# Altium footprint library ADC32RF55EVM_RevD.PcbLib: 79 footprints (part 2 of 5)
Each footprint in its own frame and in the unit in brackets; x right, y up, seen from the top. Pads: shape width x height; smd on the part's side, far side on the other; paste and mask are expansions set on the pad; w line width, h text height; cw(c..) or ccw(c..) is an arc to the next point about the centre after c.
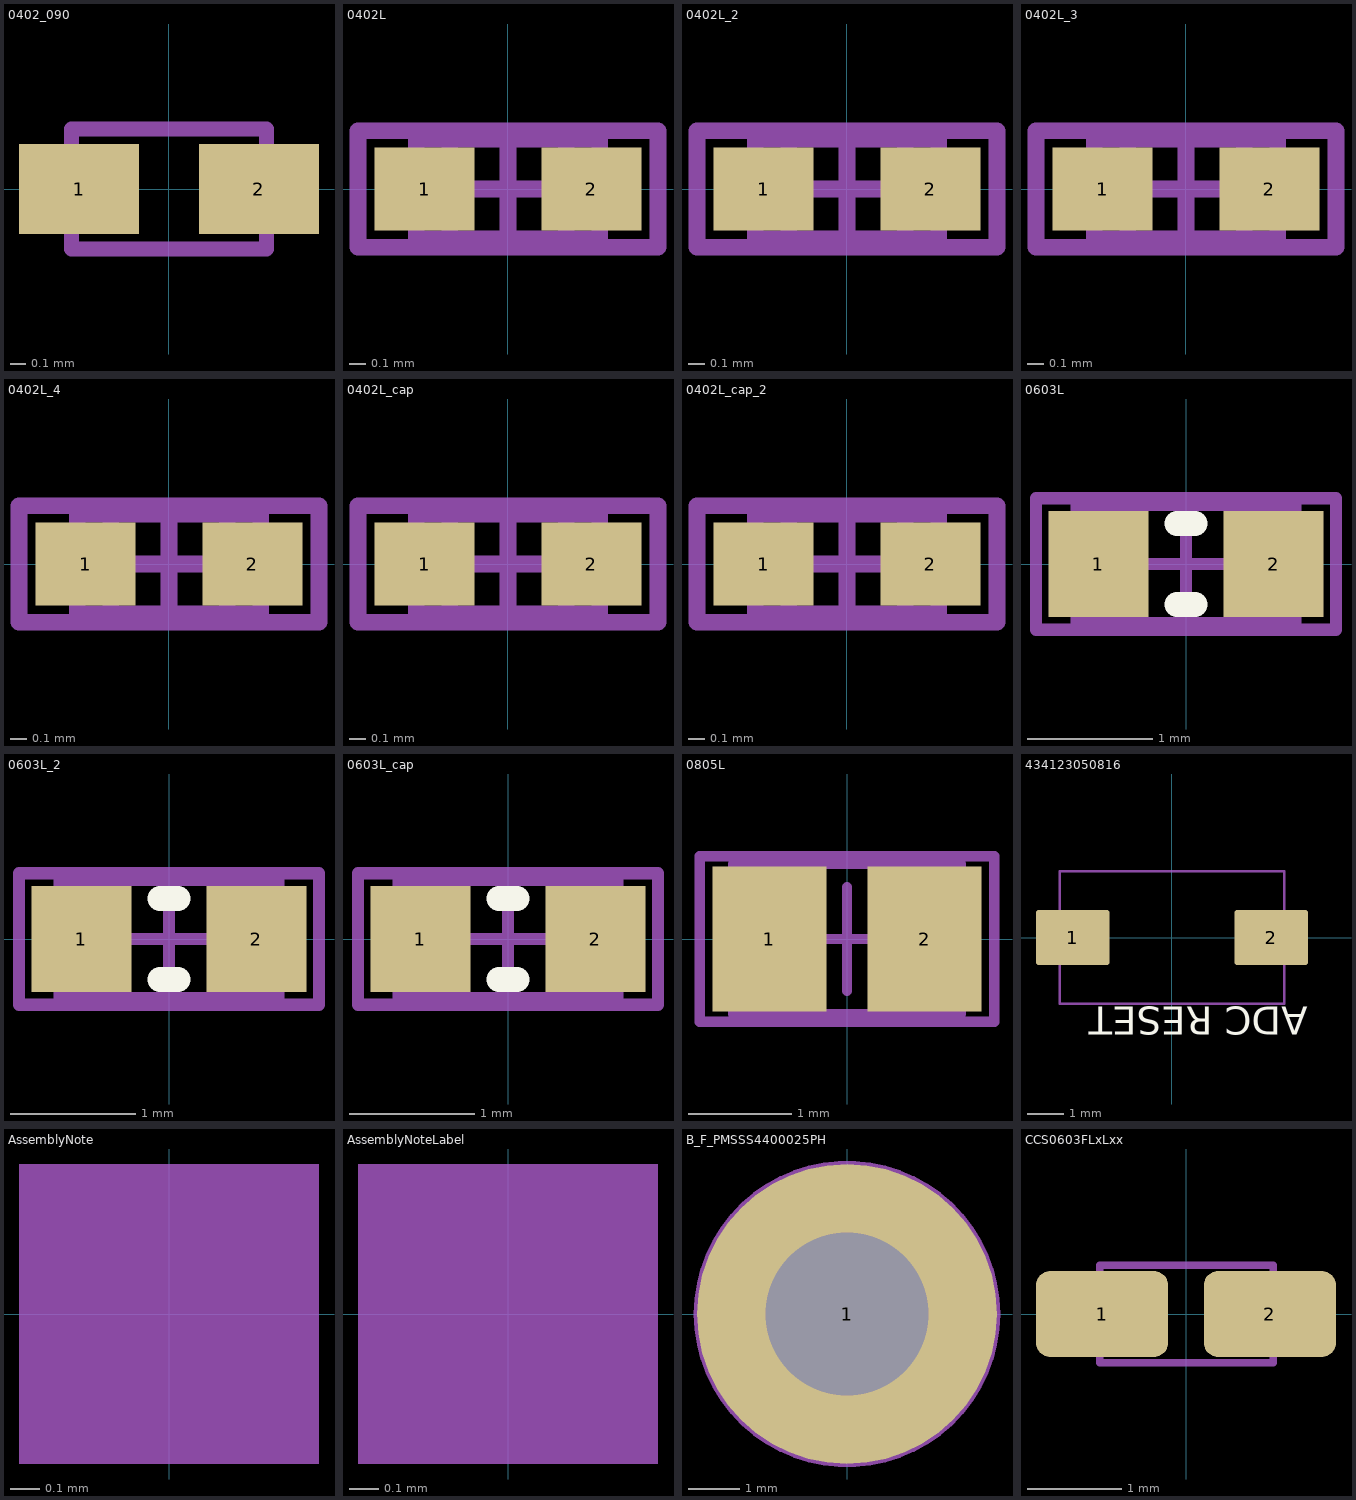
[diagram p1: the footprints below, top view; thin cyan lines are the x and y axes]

## 0402_090 [mm] "SMD, 2-Leads, Body 1x0.5mm"
height 0.9
pads (2):
  rect 0.8x0.6 smd: 1(-0.6,0) 2(0.6,0)
Mechanical 5:
  lines w0.1: -0.65,-0.4 -0.65,0.4 0.65,0.4 0.65,-0.4 -0.65,-0.4
  text ".Designator" at -0.55,-0.1 h0.3
3D body "CAPC1005X09N.step": height 0.9, standoff 0, extent -0.6,-0.35 0.6,0.35

## 0402L [mm] "0402 from SM-752 data"
height 0.6
pads (2):
  rect 0.6x0.5 smd: 1(-0.5,0) 2(0.5,0)
Mechanical 5:
  lines w0.1: -0.9,-0.35 -0.9,0.35 0.9,0.35 0.9,-0.35 -0.9,-0.35
  text ".Designator" at -0.254,0 h0.64
Mechanical 13:
  lines w0.1: -0.35,-0.3 -0.35,0.3 ; 0.35,-0.3 0.35,0.3 ; -0.55,-0.3 0.55,-0.3 0.55,0.3 -0.55,0.3 -0.55,-0.3
Mechanical 15:
  lines w0.1: -0.3,0 0.3,0 ; 0,-0.3 0,0.3 ; -0.9,-0.35 0.9,-0.35 0.9,0.35 -0.9,0.35 -0.9,-0.35
3D body: height 0.6, standoff 0, extent 0.351,-0.299 0.549,0.299
3D body: height 0.6, standoff 0, extent -0.349,-0.299 0.349,0.299
3D body: height 0.6, standoff 0, extent -0.549,-0.299 -0.351,0.299

## 0402L_2 [mm]
pads (2):
  rect 0.6x0.5 smd: 1(-0.5,0) 2(0.5,0)
Mechanical 5:
  lines w0.1: -0.9,-0.35 0.9,-0.35 0.9,0.35 -0.9,0.35 -0.9,-0.35
  text ".Designator" at -0.775,-0.225 h0.43
Mechanical 13:
  lines w0.1: -0.35,-0.3 -0.35,0.3 ; 0.35,-0.3 0.35,0.3 ; -0.55,-0.3 -0.55,0.3 0.55,0.3 0.55,-0.3 -0.55,-0.3
Mechanical 15:
  lines w0.1: -0.3,0 0.3,0 ; 0,-0.3 0,0.3 ; -0.9,-0.35 -0.9,0.35 0.9,0.35 0.9,-0.35 -0.9,-0.35
3D body: height 0.6, standoff 0, extent -0.549,-0.299 -0.351,0.299
3D body: height 0.6, standoff 0, extent -0.349,-0.299 0.349,0.299
3D body: height 0.6, standoff 0, extent 0.351,-0.299 0.549,0.299

## 0402L_3 [mm]
pads (2):
  rect 0.6x0.5 smd: 1(-0.5,0) 2(0.5,0)
Mechanical 5:
  lines w0.1: -0.9,-0.35 -0.9,0.35 0.9,0.35 0.9,-0.35 -0.9,-0.35
  text ".Designator" at -0.254,0 h0.64
Mechanical 13:
  lines w0.1: -0.35,-0.3 -0.35,0.3 ; 0.35,-0.3 0.35,0.3 ; -0.55,-0.3 0.55,-0.3 0.55,0.3 -0.55,0.3 -0.55,-0.3
Mechanical 15:
  lines w0.1: -0.3,0 0.3,0 ; 0,-0.3 0,0.3 ; -0.9,-0.35 0.9,-0.35 0.9,0.35 -0.9,0.35 -0.9,-0.35
3D body: height 0.6, standoff 0, extent 0.351,-0.299 0.549,0.299
3D body: height 0.6, standoff 0, extent -0.349,-0.299 0.349,0.299
3D body: height 0.6, standoff 0, extent -0.549,-0.299 -0.351,0.299

## 0402L_4 [mm]
pads (2):
  rect 0.6x0.5 smd: 1(-0.5,0) 2(0.5,0)
Mechanical 5:
  lines w0.1: -0.9,-0.35 0.9,-0.35 0.9,0.35 -0.9,0.35 -0.9,-0.35
  text ".Designator" at -0.254,0 h0.64
Mechanical 13:
  lines w0.1: -0.35,-0.3 -0.35,0.3 ; 0.35,-0.3 0.35,0.3 ; -0.55,-0.3 -0.55,0.3 0.55,0.3 0.55,-0.3 -0.55,-0.3
Mechanical 15:
  lines w0.1: -0.3,0 0.3,0 ; 0,-0.3 0,0.3 ; -0.9,-0.35 -0.9,0.35 0.9,0.35 0.9,-0.35 -0.9,-0.35
3D body: height 0.6, standoff 0, extent -0.549,-0.299 -0.351,0.299
3D body: height 0.6, standoff 0, extent -0.349,-0.299 0.349,0.299
3D body: height 0.6, standoff 0, extent 0.351,-0.299 0.549,0.299

## 0402L_cap [mm] "0402 from SM-752 data"
height 0.6
pads (2):
  rect 0.6x0.5 smd: 1(-0.5,0) 2(0.5,0)
Mechanical 5:
  lines w0.1: -0.9,-0.35 0.9,-0.35 0.9,0.35 -0.9,0.35 -0.9,-0.35
  text ".Designator" at -0.254,0 h0.64
Mechanical 13:
  lines w0.1: -0.35,-0.3 -0.35,0.3 ; 0.35,-0.3 0.35,0.3 ; -0.55,-0.3 -0.55,0.3 0.55,0.3 0.55,-0.3 -0.55,-0.3
Mechanical 15:
  lines w0.1: -0.3,0 0.3,0 ; 0,-0.3 0,0.3 ; -0.9,-0.35 -0.9,0.35 0.9,0.35 0.9,-0.35 -0.9,-0.35
3D body: height 0.6, standoff 0, extent 0.351,-0.299 0.549,0.299
3D body: height 0.6, standoff 0, extent -0.349,-0.299 0.349,0.299
3D body: height 0.6, standoff 0, extent -0.549,-0.299 -0.351,0.299

## 0402L_cap_2 [mm]
pads (2):
  rect 0.6x0.5 smd: 1(-0.5,0) 2(0.5,0)
Mechanical 5:
  lines w0.1: -0.9,-0.35 -0.9,0.35 0.9,0.35 0.9,-0.35 -0.9,-0.35
  text ".Designator" at -0.254,0 h0.64
Mechanical 13:
  lines w0.1: -0.35,-0.3 -0.35,0.3 ; 0.35,-0.3 0.35,0.3 ; -0.55,-0.3 0.55,-0.3 0.55,0.3 -0.55,0.3 -0.55,-0.3
Mechanical 15:
  lines w0.1: -0.3,0 0.3,0 ; 0,-0.3 0,0.3 ; -0.9,-0.35 0.9,-0.35 0.9,0.35 -0.9,0.35 -0.9,-0.35
3D body: height 0.6, standoff 0, extent -0.549,-0.299 -0.351,0.299
3D body: height 0.6, standoff 0, extent -0.349,-0.299 0.349,0.299
3D body: height 0.6, standoff 0, extent 0.351,-0.299 0.549,0.299

## 0603L [mm] "0603 from SM-752 data"
height 1
pads (2):
  rect 0.8x0.85 smd: 1(-0.7,0) 2(0.7,0)
Top Overlay:
  lines w0.2: -0.071,-0.325 0.071,-0.325 ; -0.071,0.325 0.071,0.325
Mechanical 5:
  lines w0.1: -1.2,-0.525 -1.2,0.525 1.2,0.525 1.2,-0.525 -1.2,-0.525
  text ".Designator" at -0.254,0 h0.64
Mechanical 13:
  lines w0.1: -0.55,-0.475 -0.55,0.475 ; 0.55,-0.475 0.55,0.475 ; -0.875,-0.475 -0.875,0.475 0.875,0.475 0.875,-0.475 -0.875,-0.475
Mechanical 15:
  lines w0.1: -0.475,0 0.475,0 ; 0,-0.475 0,0.475 ; -1.2,-0.525 1.2,-0.525 1.2,0.525 -1.2,0.525 -1.2,-0.525
3D body: height 1, standoff 0, extent 0.551,-0.474 0.874,0.474
3D body: height 1, standoff 0, extent -0.549,-0.474 0.549,0.474
3D body: height 1, standoff 0, extent -0.874,-0.474 -0.551,0.474

## 0603L_2 [mm]
pads (2):
  rect 0.8x0.85 smd: 1(-0.7,0) 2(0.7,0)
Top Overlay:
  lines w0.2: -0.071,-0.325 0.071,-0.325 ; -0.071,0.325 0.071,0.325
Mechanical 5:
  lines w0.1: -1.2,-0.525 -1.2,0.525 1.2,0.525 1.2,-0.525 -1.2,-0.525
  text ".Designator" at -1.05,-0.275 h0.56
Mechanical 13:
  lines w0.1: -0.55,-0.475 -0.55,0.475 ; 0.55,-0.475 0.55,0.475 ; -0.875,-0.475 -0.875,0.475 0.875,0.475 0.875,-0.475 -0.875,-0.475
Mechanical 15:
  lines w0.1: -0.475,0 0.475,0 ; 0,-0.475 0,0.475 ; -1.2,-0.525 1.2,-0.525 1.2,0.525 -1.2,0.525 -1.2,-0.525
3D body: height 1, standoff 0, extent -0.874,-0.474 -0.551,0.474
3D body: height 1, standoff 0, extent -0.549,-0.474 0.549,0.474
3D body: height 1, standoff 0, extent 0.551,-0.474 0.874,0.474

## 0603L_cap [mm] "0603 from SM-752 data"
height 1
pads (2):
  rect 0.8x0.85 smd: 1(-0.7,0) 2(0.7,0)
Top Overlay:
  lines w0.2: -0.071,-0.325 0.071,-0.325 ; -0.071,0.325 0.071,0.325
Mechanical 5:
  lines w0.1: -1.2,-0.525 1.2,-0.525 1.2,0.525 -1.2,0.525 -1.2,-0.525
  text ".Designator" at -0.254,0 h0.64
Mechanical 13:
  lines w0.1: -0.55,-0.475 -0.55,0.475 ; 0.55,-0.475 0.55,0.475 ; -0.875,-0.475 0.875,-0.475 0.875,0.475 -0.875,0.475 -0.875,-0.475
Mechanical 15:
  lines w0.1: -0.475,0 0.475,0 ; 0,-0.475 0,0.475 ; -1.2,-0.525 -1.2,0.525 1.2,0.525 1.2,-0.525 -1.2,-0.525
3D body: height 1, standoff 0, extent 0.551,-0.474 0.874,0.474
3D body: height 1, standoff 0, extent -0.549,-0.474 0.549,0.474
3D body: height 1, standoff 0, extent -0.874,-0.474 -0.551,0.474

## 0805L [mm] "0805 from SM-752 data"
height 1.45
pads (2):
  rect 1.1x1.4 smd: 1(-0.75,0) 2(0.75,0)
Mechanical 5:
  lines w0.1: -1.425,-0.8 1.425,-0.8 1.425,0.8 -1.425,0.8 -1.425,-0.8
  text ".Designator" at -1.2,-0.325 h0.64
Mechanical 13:
  lines w0.1: -0.65,-0.725 -0.65,0.725 ; 0.65,-0.725 0.65,0.725 ; -1.1,-0.725 -1.1,0.725 1.1,0.725 1.1,-0.725 -1.1,-0.725
Mechanical 15:
  lines w0.1: -0.5,0 0.5,0 ; 0,-0.5 0,0.5 ; -1.425,-0.8 -1.425,0.8 1.425,0.8 1.425,-0.8 -1.425,-0.8
3D body: height 1.45, standoff 0, extent 0.651,-0.724 1.099,0.724
3D body: height 1.45, standoff 0, extent -0.649,-0.724 0.649,0.724
3D body: height 1.45, standoff 0, extent -1.099,-0.724 -0.651,0.724

## 434123050816 [mm] "SWITCH TACTILE SPST-NO 0.05A 12V"
pads (2):
  rrect10% 2x1.5 smd mask+0.05: 1(-2.7,0) 2(2.7,0)
Top Overlay:
  text "ADC RESET" at 3.7,-1.881 h0.76
Mechanical 5:
  lines w0.07: -3.05,-1.8 3.05,-1.8 3.05,1.8 -3.05,1.8 -3.05,-1.8
  text ".Designator" at -0.127,0.339 h0.64
3D body: height 2.26, standoff 0, extent -2.7,-1.473 2.7,1.473
3D body: height 3.23, standoff 0, extent -1.7,-0.75 1.7,0.75

## AssemblyNote [mm] "Assembly Note"
Mechanical 5:
  rectangle: -0.508,-0.508 0.508,0.508
  text ".Comment" at 1.143,-0.508 h1.02
  text ".Designator" at -11.176,-0.508 h1.02

## AssemblyNoteLabel [mm] "Assembly Note for PCB Labels"
Mechanical 5:
  rectangle: -0.508,-0.508 0.508,0.508
  text "Install label in silkscreened box after final wash.  Text shall be 8 pt font.  Text shall be per the Label Table in the PDF schematic." at 1.016,-0.508 h1.02
  text ".Designator" at -11.189,-0.508 h1.02

## B_F_PMSSS4400025PH [mil] "MACHINE SCREW PAN PHILLIPS 4-40"
height 82.68
pads (1):
  round 230 hole 125: 1(0,0)
Mechanical 5:
  circle w5: c0,0 r115
  text ".Designator" at -71.85,-16.73 h40
3D body "PMSSS 440 0025 PH.stp": height 79.21, standoff -248.03, extent -109.49,-109.49 109.51,109.51

## CCS0603FLxLxx [mm]
height 4.27
pads (2):
  rrect33% 1.41x0.92 smd: 1(-0.9,0) 2(0.89,0)
Mechanical 5:
  lines w0.08: -0.927,-0.521 0.927,-0.521 ; -0.927,0.521 0.927,0.521
  text ".Designator" at -0.127,0.339 h0.64
Mechanical 13:
  lines w0.08: -0.927,-0.521 0.927,-0.521 0.927,0.521 -0.927,0.521 -0.927,-0.521
3D body "RES_CSS0603_STP.step": height 0.66, standoff 0, extent -0.927,-0.521 0.927,0.521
